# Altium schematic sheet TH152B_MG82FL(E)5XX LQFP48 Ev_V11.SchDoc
size 279 x 193 mm; PageSetup: Record=PageOptions|CenterHorizontal=True|CenterVertical=True|PrintScale=1.02|XCorrection=1.00|YCorrection=1.00|PrintKind=0|BorderSize=5000000|LeftOffset=0|BottomOffset=0|Orientation=2|PaperLength=1000|PaperWidth=1000|Scale=100|PaperSource=7|PrintQuality=-4|MediaType=1|DitherType=10|PaperKind=A4 (210 x 297 mm)|PrintScaleMode=1
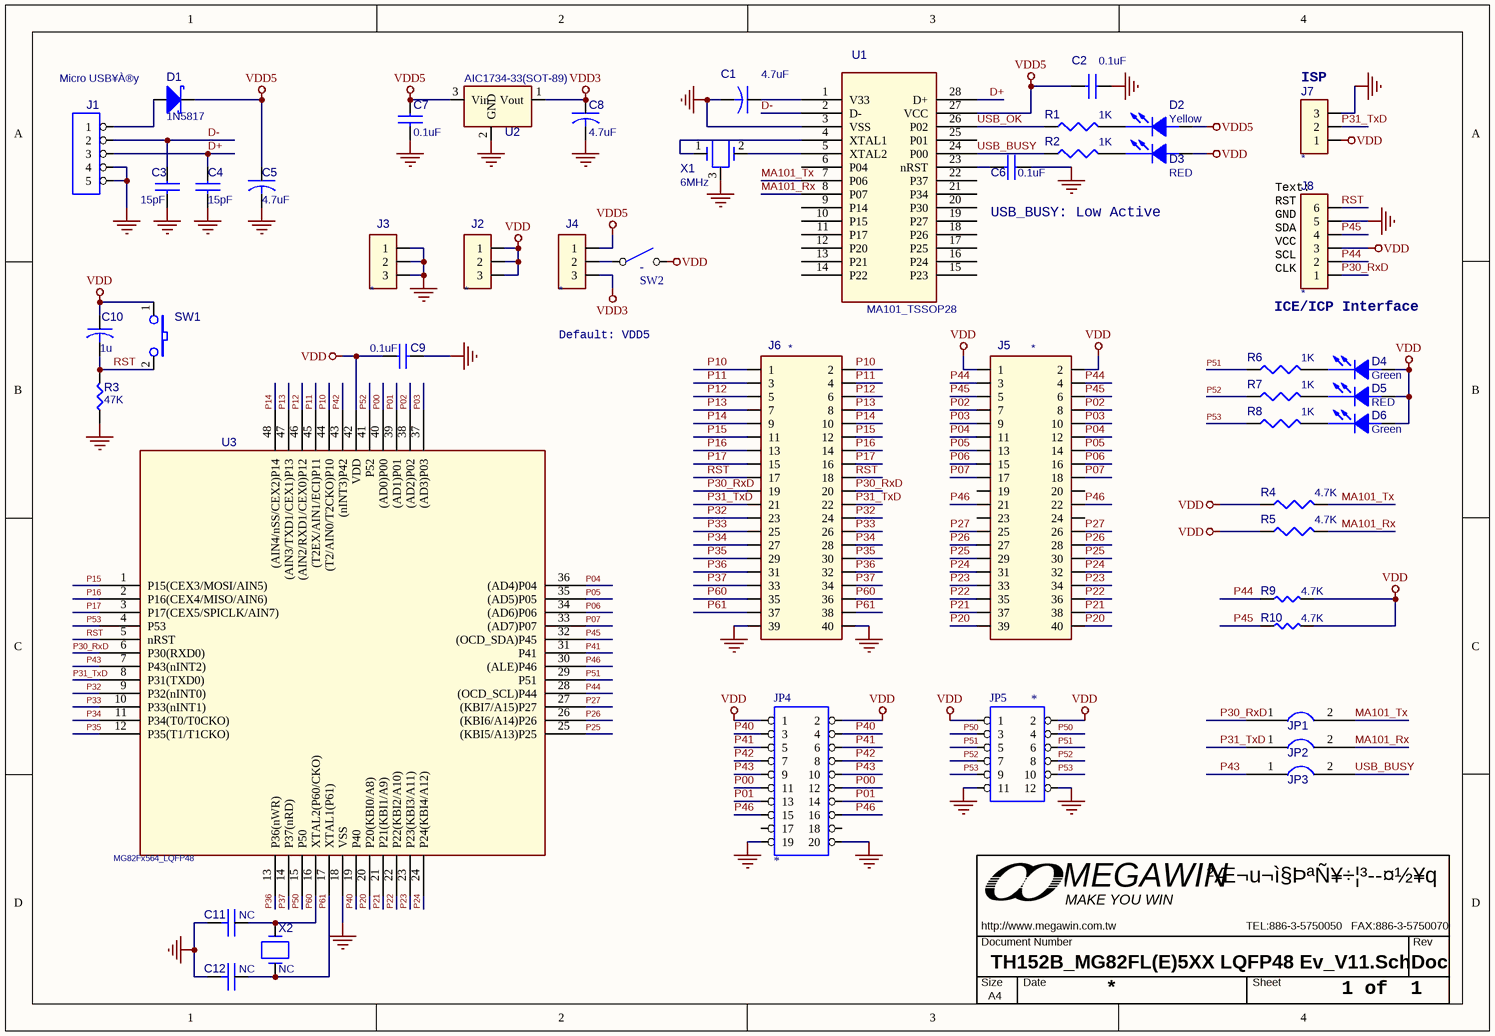
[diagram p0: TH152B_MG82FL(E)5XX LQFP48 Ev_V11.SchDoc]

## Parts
C1  4.7uF  [0805C]
C2  0.1uF  [0805C]
C3  15pF  [0805C]
C4  15pF  [0805C]
C5  4.7uF  [1206C]
C6  0.1uF  [0805C]
C7  0.1uF  [0805C]
C8  4.7uF  [0805C]
C9  0.1uF  [0805C]
C10  1u  [0805C]
C11  NC  [0805C]
C12  NC  [0805C]
D1  1N5817  [D5817_SMD_1]
D2  Yellow  [0805D]
D3  RED  [0805D]
D4  Green  [0805D]
D5  RED  [0805D]
D6  Green  [0805D]
J1  Micro USB¥À®y  [PC5p200_90]
J2  *  [PS3P254]
J3  *  [PS3P254]
J4  *  [JUMP3_SMD]
J5  *  [PS20X2P254]
J6  *  [PS20X2P254]
J7  *  [PS3P254f_90]
J8  *  [PS6P254F_90]
JP1  JUMPER2  [PS2P254]  (value not drawn)
JP2  JUMPER2  [PS2P254]  (value not drawn)
JP3  JUMPER2  [PS2P254]  (value not drawn)
JP4  *  [PS10X2P254]
JP5  *  [PS6X2P254]
MW1  OrgName: ²Æ¬u¬ì§ÞªÑ¥÷¦³­­¤½¥q  OrgAddr1: MEGAWIN  OrgAddr3: TEL:886-3-5750050   FAX:886-3-5750070  Page Size: A4  [MEGAWIN_T]  (hidden comment: MW-A4)  (no BOM)
R1  1K  [0805R]
R2  1K  [0805R]
R3  47K  [0805R]
R4  4.7K  [0805R]
R5  4.7K  [0805R]
R6  1K  [0805R]
R7  1K  [0805R]
R8  1K  [0805R]
R9  4.7K  [0805R]
R10  4.7K  [0805R]
SW1  SW TACT-SPST  [SW_T_2P]  (value not drawn)
SW2  -  [DIP2_SW]
U1  MA101_TSSOP28  [TSSOP28_170P065]
U2  AIC1734-33(SOT-89)  [SOT89]
U3  MG82Fx564_LQFP48  [LQFP48_7X7_050]
X1  6MHz  [X3P]
X2  NC  [X49U]

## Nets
GND_POWER: C1.2 C2.1 C3.2 C4.2 C5.2 C6.1 C7.2 C8.2 C9.2 C11.2 C12.2 J1.4 J1.5 J3.1 J3.2 J3.3 J6.39 J6.40 J7.3 J8.5 JP4.19 JP4.20 JP5.11 JP5.12 R3.1 U1.3(VSS) U2.2(GND) U3.18(VSS) X1.3
VDD: C9.1 C10.1(POS) D3.1(ANODE) D4.1(ANODE) D5.1(ANODE) D6.1(ANODE) J2.1 J2.2 J2.3 J5.1 J5.2 J7.1 J8.3 JP4.1 JP4.2 JP5.1 JP5.2 R4.1 R5.1 R9.2 R10.2 SW1.1 SW2.2(NO) U3.42(VDD)
VDD3: C8.1 J4.3 U2.1(Vout)
VDD5: C2.2 C5.1 C7.1 D1.2(K) D2.1(ANODE) J4.1 U1.27(VCC) U2.3(Vin)
D+: C4.1 J1.3 U1.28(D+)
D-: C3.1 J1.2 U1.2(D-)
MA101_Rx: JP2.2 R5.2 U1.8(P07)
MA101_Tx: JP1.2 R4.2 U1.7(P06)
P00: JP4.11 JP4.12 U3.40((AD0)P00)
P01: JP4.13 JP4.14 U3.39((AD1)P01)
P02: J5.7 J5.8 U3.38((AD2)P02)
P03: J5.9 J5.10 U3.37((AD3)P03)
P04: J5.11 J5.12 U3.36((AD4)P04)
P05: J5.13 J5.14 U3.35((AD5)P05)
P06: J5.15 J5.16 U3.34((AD6)P06)
P07: J5.17 J5.18 U3.33((AD7)P07)
P10: J6.1 J6.2 U3.44((T2/AIN0/T2CKO)P10)
P11: J6.3 J6.4 U3.45((T2EX/AIN1/ECI)P11)
P12: J6.5 J6.6 U3.46((AIN2/RXD1/CEX0)P12)
P13: J6.7 J6.8 U3.47((AIN3/TXD1/CEX1)P13)
P14: J6.9 J6.10 U3.48((AIN4/nSS/CEX2)P14)
P15: J6.11 J6.12 U3.1(P15(CEX3/MOSI/AIN5))
P16: J6.13 J6.14 U3.2(P16(CEX4/MISO/AIN6))
P17: J6.15 J6.16 U3.3(P17(CEX5/SPICLK/AIN7))
P20: J5.39 J5.40 U3.20(P20(KBI0/A8))
P21: J5.37 J5.38 U3.21(P21(KBI1/A9))
P22: J5.35 J5.36 U3.22(P22(KBI2/A10))
P23: J5.33 J5.34 U3.23(P23(KBI3/A11))
P24: J5.31 J5.32 U3.24(P24(KBI4/A12))
P25: J5.29 J5.30 U3.25((KBI5/A13)P25)
P26: J5.27 J5.28 U3.26((KBI6/A14)P26)
P27: J5.25 J5.26 U3.27((KBI7/A15)P27)
P30_RxD: J6.19 J6.20 J8.1 JP1.1 U3.6(P30(RXD0))
P31_TxD: J6.21 J6.22 J7.2 JP2.1 U3.8(P31(TXD0))
P32: J6.23 J6.24 U3.9(P32(nINT0))
P33: J6.25 J6.26 U3.10(P33(nINT1))
P34: J6.27 J6.28 U3.11(P34(T0/T0CKO))
P35: J6.29 J6.30 U3.12(P35(T1/T1CKO))
P36: J6.31 J6.32 U3.13(P36(nWR))
P37: J6.33 J6.34 U3.14(P37(nRD))
P40: JP4.3 JP4.4 U3.19(P40)
P41: JP4.5 JP4.6 U3.31(P41)
P42: JP4.7 JP4.8 U3.43((nINT3)P42)
P43: JP3.1 JP4.9 JP4.10 U3.7(P43(nINT2))
P44: J5.3 J5.4 J8.2 R9.1 U3.28((OCD_SCL)P44)
P45: J5.5 J5.6 J8.4 R10.1 U3.32((OCD_SDA)P45)
P46: J5.21 J5.22 JP4.15 JP4.16 U3.30((ALE)P46)
P50: JP5.3 JP5.4 U3.15(P50)
P51: JP5.5 JP5.6 R6.1 U3.29(P51)
P52: JP5.7 JP5.8 R7.1 U3.41(P52)
P53: JP5.9 JP5.10 R8.1 U3.4(P53)
P60: C11.1 J6.35 J6.36 U3.16(XTAL2(P60/CKO)) X2.1
P61: C12.1 J6.37 J6.38 U3.17(XTAL1(P61)) X2.2
RST: C10.2(NEG) J6.17 J6.18 J8.6 R3.2 SW1.2 U3.5(nRST)
USB_BUSY: JP3.2 R2.1 U1.24(P00)
USB_OK: R1.1 U1.26(P02)
NetC1_1: C1.1 U1.1(V33)
NetC6_2: C6.2 U1.23(nRST)
NetD1_1: D1.1(A) J1.1
NetD2_2: D2.2(CATHODE) R1.2
NetD3_2: D3.2(CATHODE) R2.2
NetD4_2: D4.2(CATHODE) R6.2
NetD5_2: D5.2(CATHODE) R7.2
NetD6_2: D6.2(CATHODE) R8.2
NetJ4_2: J4.2 SW2.1(COMMON)
NetU1_4: U1.4(XTAL1) X1.1
NetU1_5: U1.5(XTAL2) X1.2

Not connected (* = marked no-connect by the designer): J5 19 20 23 24; JP4 17 18; U1 6(P04) 9(P14) 10(P15) 11(P17) 12(P20) 13(P21) 14(P22) 15(P23) 16(P24) 17(P25) 18(P26) 19(P27) 20(P30) 21(P34) 22(P37) 25(P01)

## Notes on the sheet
- (near J7) ISP
- USB_BUSY: Low Active
- (near J8) ICE/ICP Interface
- (near J8) Text:
  RST
  GND
  SDA
  VCC
  SCL
  CLK
- Default: VDD5
- 1 of  1

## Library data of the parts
C1 C5 C8 = CAP
C2-C4 C6 C7 C9 = CAP NP
C10 = C
C11 C12 = C NP
D1 = DIODE_ZD: Schottky Diode
D2-D6 = LED
J1 = CON5: Connector
J2-J4 J7 = CON3
J5 J6 = CON40A
J8 = CON6
JP4 = CON10X2
JP5 = CON6X2
R1 R2 R4-R8 = R_Dup1
R3 R9 R10 = R
SW2 = SW-2
U2 = AIC1734-33(SOT-89)_0
X1 = CRYSTAL_RC
X2 = CRYSTAL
